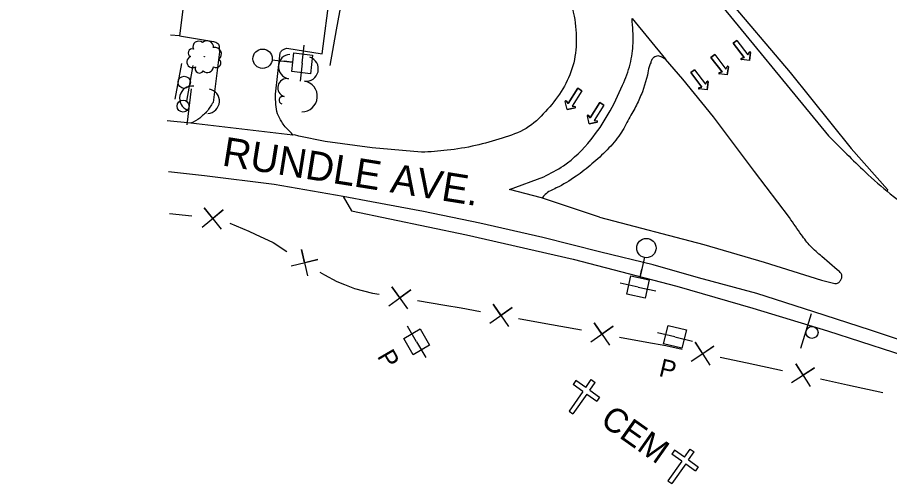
# Model space of a CAD drawing. Extents: x 1746010 to 1754829, y 655801 to 663091.
# Drawn here: x 1748407 to 1748767.9, y 660989.4 to 661182.3 of the extents above; entities that cross this region are included whole.
import ezdxf

# ---------------------------------------------------------------- set-up
doc = ezdxf.new("R2010")
doc.units = 0
for name, color, linetype in [('SURVEY - AERIAL SURVEY - Photo Control - Points - Locators', 7, 'Continuous'), ('SURVEY - AERIAL SURVEY - Photo Control with Text', 7, 'Continuous'), ('SURVEY - CENTERLINE - Existing Roads - Development', 7, 'Continuous'), ('SURVEY - CENTERLINE - Existing Roads Curve Text', 7, 'Continuous'), ('SURVEY - CENTERLINE - Existing Roads Text', 7, 'Continuous'), ('SURVEY - CONTROL - Points - Numbers', 7, 'Continuous'), ('SURVEY - DRAINAGE - Area Shapes - Points - Elevations', 7, 'Continuous')]:
    doc.layers.add(name, color=color, linetype=linetype)

msp = doc.modelspace()

# ---------------------------------------------------------------- linework, layer by layer
at = {"layer": 'SURVEY - AERIAL SURVEY - Photo Control - Points - Locators'}
for points in [[(1748406.97, 661541.06), (1748446.41, 661490.26), (1748508.74, 661414.72), (1748569.86, 661344.49), (1748590.82, 661319.8), (1748726.77, 661159.53), (1748751.93, 661128.01), (1748766.95, 661111.05), (1748766.91, 661110.24)], [(1748543.22, 661365.16), (1748594.47, 661308.59), (1748642.89, 661253.78), (1748692.5, 661194.4), (1748742.62, 661133.3)], [(1748518.42, 661169.62), (1748533.03, 661167.27), (1748536.2, 661191.62), (1748539.76, 661216.56), (1748542.46, 661233.46)], [(1748496.01, 661230.52), (1748481.14, 661231.68), (1748474.06, 661174.67), (1748488.07, 661172.42)], [(1748661.29, 661181.86), (1748675.13, 661165.08)], [(1748490.62, 661168.12), (1748487.93, 661147.18)], [(1748513.7, 661150.58), (1748515.68, 661167.64)], [(1748726.41, 661099.45), (1748712.04, 661118.62), (1748695, 661141.22), (1748682.26, 661156.79), (1748675.13, 661165.08), (1748673.31, 661166.09), (1748672.09, 661166.46)], [(1748667.7, 661158.5), (1748665.59, 661151.48)], [(1748478.78, 661138.57), (1748468.89, 661139.58)], [(1748520.94, 661133.63), (1748478.78, 661138.57)], [(1748574.2, 661126.49), (1748553.7, 661128.42), (1748534.25, 661130.98), (1748523.46, 661133.24), (1748521.67, 661133.71), (1748520.94, 661133.63)], [(1748541.72, 661108.22), (1748513.15, 661113.14), (1748484.42, 661116.74), (1748469.44, 661118.42)], [(1748647.88, 661099.66), (1748623.79, 661107.64), (1748610.62, 661111.11), (1748624.77, 661116.3)], [(1748842.21, 661022.63), (1748822.81, 661030.17), (1748796.81, 661040.14), (1748778.58, 661046.61), (1748759.98, 661052.88), (1748736.59, 661060.44), (1748712.91, 661068.1), (1748688.81, 661074.54), (1748669.98, 661079.87), (1748648.34, 661085.22), (1748624.42, 661091.25), (1748598.28, 661097.15), (1748575.03, 661102), (1748553.53, 661106.02), (1748541.72, 661108.22)], [(1748541.72, 661108.22), (1748545.25, 661102.3), (1748592.74, 661092.3), (1748636.87, 661082.32), (1748679.9, 661071.09), (1748711.25, 661062), (1748742.12, 661052.58), (1748783.15, 661039.32), (1748819.11, 661026.13), (1748839.93, 661016.87), (1748840.62, 661016.6)], [(1748647.88, 661099.66), (1748691.06, 661088.31), (1748715.95, 661081.07), (1748739.71, 661073.63), (1748745.15, 661072.22)], [(1748746.23, 661077.86), (1748739.88, 661083.39)]]:
    msp.add_lwpolyline(points, dxfattribs=at)
for points in [[(1748629.63, 661201.31), (1748633.06, 661195.53), (1748637.33, 661182.83), (1748638.2, 661171.57), (1748636.45, 661161.01), (1748631.94, 661151.62), (1748625.47, 661143.35), (1748617.47, 661136.42), (1748607.57, 661132.33), (1748596.53, 661129.3), (1748584.78, 661127.33), (1748574.2, 661126.49)], [(1748624.77, 661116.3), (1748632.94, 661120.97), (1748644.26, 661131.71), (1748651.45, 661142.23), (1748657.39, 661154.29), (1748660.48, 661163.05), (1748661.7, 661171.73), (1748661.29, 661181.86)], [(1748488.07, 661172.42), (1748489.87, 661171.51), (1748490.34, 661170.87), (1748490.44, 661169.84), (1748490.62, 661168.12)], [(1748515.68, 661167.64), (1748516.49, 661168.78), (1748517.59, 661169.35), (1748518.42, 661169.62)], [(1748672.09, 661166.46), (1748670.33, 661165.75), (1748669.52, 661164.85), (1748669.01, 661163.58), (1748668.41, 661161.94), (1748667.7, 661158.5)], [(1748520.94, 661133.63), (1748519.64, 661135.16), (1748517.74, 661137.06), (1748516.31, 661139.18), (1748514.59, 661142.42), (1748513.94, 661146.26), (1748513.7, 661150.58)], [(1748665.59, 661151.48), (1748663.14, 661146.08), (1748660.02, 661140.39), (1748656.43, 661134.01), (1748651.01, 661127.58), (1748644.7, 661121.67), (1748638.11, 661116.58), (1748629.91, 661111.73), (1748625.35, 661109.05), (1748624.06, 661107.55)], [(1748487.93, 661147.18), (1748486.61, 661145.17), (1748485.47, 661143.47), (1748483.97, 661142.07), (1748482.41, 661140.64), (1748478.78, 661138.57)], [(1748742.62, 661133.3), (1748757.79, 661118.4), (1748768.18, 661109.29), (1748782.04, 661099.44), (1748805.67, 661082.87), (1748823.6, 661073.1), (1748848.74, 661060.68)], [(1748739.88, 661083.39), (1748735.16, 661087.62), (1748731.42, 661092.34), (1748726.41, 661099.45)], [(1748745.15, 661072.22), (1748746.63, 661072.44), (1748747.52, 661073.44), (1748747.89, 661073.96), (1748748.18, 661075.12), (1748747.81, 661076.27), (1748746.23, 661077.86)]]:
    msp.add_spline(points, degree=3, dxfattribs=at)
at = {"layer": 'SURVEY - AERIAL SURVEY - Photo Control with Text'}
for p, q in [((1748472.29, 661148.52), (1748474.99, 661163.28)), ((1748477.01, 661147.66), (1748479.71, 661162.41)), ((1748478.85, 661152.82), (1748477.04, 661137.93)), ((1748731.2, 661045.45), (1748735.62, 661059.79))]:
    msp.add_line(p, q, dxfattribs=at)
for centre, radius in [((1748476, 661155.47), 2.54), ((1748475.5, 661145.63), 2.5), ((1748735.76, 661051.94), 2.5)]:
    msp.add_circle(centre, radius, dxfattribs=at)
at = {"layer": 'SURVEY - CENTERLINE - Existing Roads - Development'}
for p, q in [((1748638.06, 661032.04), (1748636.91, 661030.41)), ((1748642.15, 661029.16), (1748638.06, 661032.04)), ((1748642.15, 661029.16), (1748644.45, 661032.43)), ((1748643.78, 661028.01), (1748646.09, 661031.28)), ((1748644.45, 661032.43), (1748646.09, 661031.28)), ((1748640.99, 661027.53), (1748635.23, 661019.35)), ((1748640.99, 661027.53), (1748636.91, 661030.41)), ((1748643.78, 661028.01), (1748647.87, 661025.12)), ((1748642.63, 661026.37), (1748636.86, 661018.2)), ((1748642.63, 661026.37), (1748646.72, 661023.49)), ((1748647.87, 661025.12), (1748646.72, 661023.49)), ((1748635.23, 661019.35), (1748636.86, 661018.2)), ((1748678.92, 661003.22), (1748677.77, 661001.58)), ((1748683.01, 661000.34), (1748678.92, 661003.22)), ((1748683.01, 661000.34), (1748685.31, 661003.61)), ((1748684.64, 660999.18), (1748686.95, 661002.45)), ((1748685.31, 661003.61), (1748686.95, 661002.45)), ((1748681.85, 660998.7), (1748676.09, 660990.53)), ((1748681.85, 660998.7), (1748677.77, 661001.58)), ((1748684.64, 660999.18), (1748688.73, 660996.3)), ((1748683.49, 660997.55), (1748677.72, 660989.38)), ((1748683.49, 660997.55), (1748687.57, 660994.67)), ((1748688.73, 660996.3), (1748687.57, 660994.67)), ((1748676.09, 660990.53), (1748677.72, 660989.38))]:
    msp.add_line(p, q, dxfattribs=at)
for points in [[(1748540.97, 661188.37), (1748538.92, 661177.16)], [(1748538.92, 661177.16), (1748536.22, 661162.41)], [(1748474.06, 661174.67), (1748470.31, 661175.04)], [(1748483.37, 661095.58), (1748492.11, 661102.64), (1748487.79, 661099.11), (1748484.26, 661103.52), (1748491.22, 661094.71)], [(1748469.9, 661101.15), (1748479.15, 661100.16)], [(1748494.88, 661097.11), (1748502.7, 661093.91), (1748505.36, 661092.64)], [(1748505.36, 661092.64), (1748512.73, 661089.1), (1748518.5, 661085.48)], [(1748520.29, 661079.52), (1748531.24, 661082.08), (1748525.81, 661080.77), (1748524.56, 661086.27), (1748526.97, 661075.32)], [(1748532.12, 661076.92), (1748534.03, 661075.72), (1748539.15, 661073.04), (1748542.27, 661071.78)], [(1748542.27, 661071.78), (1748546.45, 661070.08), (1748553.96, 661068.21), (1748556.66, 661067.77)], [(1748560.61, 661062.96), (1748569.73, 661069.54), (1748565.22, 661066.24), (1748561.94, 661070.83), (1748568.4, 661061.66)], [(1748572.53, 661065.12), (1748583.77, 661063.25)], [(1748583.77, 661063.25), (1748590.58, 661062.11), (1748598.54, 661060.65)], [(1748602.41, 661055.77), (1748611.64, 661062.19), (1748607.07, 661058.97), (1748603.87, 661063.62), (1748610.18, 661054.34)], [(1748614.37, 661057.73), (1748625.58, 661055.67)], [(1748625.58, 661055.67), (1748640.32, 661052.95)], [(1748644.2, 661048.08), (1748653.42, 661054.5), (1748648.86, 661051.28), (1748645.66, 661055.93), (1748651.96, 661046.65)], [(1748656.15, 661050.04), (1748667.36, 661047.97)], [(1748667.36, 661047.97), (1748675.27, 661046.51), (1748682.07, 661045.06)], [(1748685.79, 661040.07), (1748695.2, 661046.22), (1748690.55, 661043.14), (1748687.48, 661047.88), (1748693.51, 661038.42)], [(1748697.8, 661041.69), (1748708.94, 661039.3)], [(1748708.94, 661039.3), (1748723.6, 661036.16)], [(1748727.3, 661031.21), (1748736.75, 661037.3), (1748732.08, 661034.24), (1748729.04, 661039), (1748735.01, 661029.5)], [(1748739.32, 661032.74), (1748750.44, 661030.28)], [(1748750.44, 661030.28), (1748765.08, 661027.04)]]:
    msp.add_lwpolyline(points, dxfattribs=at)
at = {"layer": 'SURVEY - CENTERLINE - Existing Roads Curve Text'}
for p, q in [((1748524.81, 661163.35), (1748525.67, 661170.81)), ((1748512.29, 661164.8), (1748520.94, 661163.8)), ((1748520.54, 661163.85), (1748517.36, 661164.21)), ((1748524.81, 661163.35), (1748523.95, 661155.9)), ((1748666.41, 661083.05), (1748664.59, 661074.54)), ((1748664.67, 661074.94), (1748665.34, 661078.06)), ((1748663.77, 661070.73), (1748656.44, 661072.3)), ((1748663.77, 661070.73), (1748671.11, 661069.16)), ((1748572.16, 661048.06), (1748568.41, 661054.55)), ((1748679.07, 661050.05), (1748671.78, 661051.79)), ((1748679.07, 661050.05), (1748686.37, 661048.32)), ((1748572.16, 661048.06), (1748575.92, 661041.57))]:
    msp.add_line(p, q, dxfattribs=at)
for points in [[(1748528.24, 661159.03), (1748520.49, 661159.93), (1748521.38, 661167.68), (1748529.13, 661166.78)], [(1748659.14, 661067.73), (1748660.77, 661075.36), (1748668.4, 661073.73), (1748666.77, 661066.1)], [(1748573.58, 661053.39), (1748577.49, 661046.64), (1748570.74, 661042.73), (1748566.83, 661049.48)], [(1748676.18, 661054.75), (1748683.77, 661052.95), (1748681.96, 661045.36), (1748674.37, 661047.16)]]:
    msp.add_lwpolyline(points, close=True, dxfattribs=at)
for centre in [(1748508.42, 661165.24), (1748667.23, 661086.87)]:
    msp.add_circle(centre, 4, dxfattribs=at)
at = {"layer": 'SURVEY - CENTERLINE - Existing Roads Text'}
msp.add_circle((1748484.29, 661166.05), 0.0826, dxfattribs=at)
for centre, radius, start, end in [((1748481.94, 661170.15), 2.37, 47.6043, 204.3932), ((1748485.41, 661169.97), 2.7, 356.657, 134.1813), ((1748479.22, 661167.65), 1.63, 69.7205, 248.4661), ((1748488.72, 661167.21), 2.68, 307.5529, 103.3913), ((1748479.42, 661163.91), 2.36, 109.7411, 303.1608), ((1748489.16, 661163.51), 1.98, 237.8058, 52.806), ((1748520.08, 661161.97), 5.1, 94.1554, 259.8138), ((1748520.08, 661161.97), 5.1, 94.1554, 259.8138), ((1748526.38, 661161), 5.1, 262.5893, 71.5564), ((1748526.38, 661161), 5.1, 262.5893, 71.5564), ((1748482.3, 661161.1), 1.8, 152.3598, 329.679), ((1748485.57, 661162.08), 2.55, 227.6469, 354.4925), ((1748518.51, 661153.19), 3.82, 79.8529, 251.5352), ((1748518.51, 661153.19), 3.82, 79.8529, 251.5352), ((1748479.16, 661148.78), 5.1, 81.6232, 250.5903), ((1748479.16, 661148.78), 5.1, 81.6232, 250.5903), ((1748524.7, 661149.67), 6.37, 269.3439, 80.8203), ((1748524.7, 661149.67), 6.37, 269.3439, 80.8203), ((1748485.45, 661147.69), 5.1, 273.2824, 78.9407), ((1748485.45, 661147.69), 5.1, 273.2824, 78.9407), ((1748516.84, 661148.04), 1.59, 73.2454, 253.2454), ((1748516.84, 661148.04), 1.59, 73.2454, 253.2454)]:
    msp.add_arc(centre, radius, start, end, dxfattribs=at)
at = {"layer": 'SURVEY - DRAINAGE - Area Shapes - Points - Elevations'}
for p, q in [((1748703.09, 661171.63), (1748704.65, 661172.83)), ((1748704.65, 661172.83), (1748703.09, 661171.63)), ((1748707.69, 661165.68), (1748703.09, 661171.63)), ((1748703.09, 661171.63), (1748707.69, 661165.68)), ((1748704.65, 661172.83), (1748709.25, 661166.88)), ((1748704.65, 661172.83), (1748709.25, 661166.88)), ((1748709.25, 661166.88), (1748709.86, 661167.95)), ((1748709.25, 661166.88), (1748709.86, 661167.95)), ((1748693.94, 661165.73), (1748695.5, 661166.93)), ((1748695.5, 661166.93), (1748693.94, 661165.73)), ((1748698.54, 661159.77), (1748693.94, 661165.73)), ((1748693.94, 661165.73), (1748698.54, 661159.77)), ((1748695.5, 661166.93), (1748700.1, 661160.97)), ((1748695.5, 661166.93), (1748700.1, 661160.97)), ((1748706.5, 661165.35), (1748707.69, 661165.68)), ((1748707.69, 661165.68), (1748706.5, 661165.35)), ((1748709.89, 661164.44), (1748706.54, 661164.87)), ((1748709.89, 661164.44), (1748706.54, 661164.87)), ((1748710.32, 661167.79), (1748709.89, 661164.44)), ((1748709.89, 661164.44), (1748710.32, 661167.79)), ((1748685.57, 661159.49), (1748687.12, 661160.69)), ((1748687.12, 661160.69), (1748685.57, 661159.49)), ((1748687.12, 661160.69), (1748691.72, 661154.73)), ((1748687.12, 661160.69), (1748691.72, 661154.73)), ((1748700.1, 661160.97), (1748700.71, 661162.04)), ((1748700.1, 661160.97), (1748700.71, 661162.04)), ((1748701.17, 661161.89), (1748700.73, 661158.54)), ((1748700.73, 661158.54), (1748701.17, 661161.89)), ((1748690.16, 661153.53), (1748685.57, 661159.49)), ((1748685.57, 661159.49), (1748690.16, 661153.53)), ((1748697.35, 661159.45), (1748698.54, 661159.77)), ((1748698.54, 661159.77), (1748697.35, 661159.45)), ((1748700.73, 661158.54), (1748697.38, 661158.97)), ((1748700.73, 661158.54), (1748697.38, 661158.97)), ((1748688.98, 661153.21), (1748690.16, 661153.53)), ((1748690.16, 661153.53), (1748688.98, 661153.21)), ((1748691.72, 661154.73), (1748692.33, 661155.8)), ((1748691.72, 661154.73), (1748692.33, 661155.8)), ((1748692.79, 661155.65), (1748692.36, 661152.3)), ((1748692.36, 661152.3), (1748692.79, 661155.65)), ((1748634.82, 661146.68), (1748638.84, 661153.04)), ((1748638.84, 661153.04), (1748634.82, 661146.68)), ((1748640.51, 661151.98), (1748636.48, 661145.63)), ((1748640.51, 661151.98), (1748636.48, 661145.63)), ((1748638.84, 661153.04), (1748640.51, 661151.98)), ((1748640.51, 661151.98), (1748638.84, 661153.04)), ((1748692.36, 661152.3), (1748689.01, 661152.73)), ((1748692.36, 661152.3), (1748689.01, 661152.73)), ((1748634.41, 661144.2), (1748633.67, 661147.49)), ((1748634.41, 661144.2), (1748633.67, 661147.49)), ((1748634.11, 661147.69), (1748634.82, 661146.68)), ((1748634.82, 661146.68), (1748634.11, 661147.69)), ((1748643.94, 661140.74), (1748647.97, 661147.1)), ((1748647.97, 661147.1), (1748643.94, 661140.74)), ((1748647.97, 661147.1), (1748649.63, 661146.04)), ((1748649.63, 661146.04), (1748647.97, 661147.1)), ((1748637.7, 661144.94), (1748634.41, 661144.2)), ((1748634.41, 661144.2), (1748637.7, 661144.94)), ((1748636.48, 661145.63), (1748637.69, 661145.42)), ((1748636.48, 661145.63), (1748637.69, 661145.42)), ((1748649.63, 661146.04), (1748645.61, 661139.69)), ((1748649.63, 661146.04), (1748645.61, 661139.69)), ((1748643.54, 661138.26), (1748642.8, 661141.55)), ((1748643.54, 661138.26), (1748642.8, 661141.55)), ((1748643.24, 661141.75), (1748643.94, 661140.74)), ((1748643.94, 661140.74), (1748643.24, 661141.75)), ((1748646.83, 661139), (1748643.54, 661138.26)), ((1748643.54, 661138.26), (1748646.83, 661139)), ((1748645.61, 661139.69), (1748646.82, 661139.48)), ((1748645.61, 661139.69), (1748646.82, 661139.48))]:
    msp.add_line(p, q, dxfattribs=at)
for centre, start, end in [((1748710.07, 661167.82), 352.6523, 150.1454), ((1748710.07, 661167.82), 352.6523, 150.1454), ((1748706.57, 661165.12), 105.204, 262.6523), ((1748706.57, 661165.12), 105.204, 262.6523), ((1748700.92, 661161.92), 352.6523, 150.1454), ((1748700.92, 661161.92), 352.6523, 150.1454), ((1748697.41, 661159.21), 105.204, 262.6523), ((1748697.41, 661159.21), 105.204, 262.6523), ((1748692.55, 661155.68), 352.6523, 150.1454), ((1748692.55, 661155.68), 352.6523, 150.1454), ((1748689.04, 661152.97), 105.204, 262.6523), ((1748689.04, 661152.97), 105.204, 262.6523), ((1748633.91, 661147.55), 35.1957, 192.644), ((1748633.91, 661147.55), 35.1957, 192.644), ((1748637.65, 661145.18), 282.644, 80.1371), ((1748637.65, 661145.18), 282.644, 80.1371), ((1748643.03, 661141.61), 35.1957, 192.644), ((1748643.03, 661141.61), 35.1957, 192.644), ((1748646.78, 661139.24), 282.644, 80.1371), ((1748646.78, 661139.24), 282.644, 80.1371)]:
    msp.add_arc(centre, 0.246, start, end, dxfattribs=at)

# ---------------------------------------------------------------- texts
at = {"layer": 'SURVEY - CENTERLINE - Existing Roads - Development'}
msp.add_text('CEM', height=10.001, rotation=324.7996, dxfattribs=at).set_placement((1748647.67, 661014.25))
at = {"layer": 'SURVEY - CENTERLINE - Existing Roads Curve Text'}
for rotation, p in [(300.0757, (1748555.64, 661042.08)), (346.6107, (1748672.05, 661033.94))]:
    msp.add_text('P', height=7.48, rotation=rotation, dxfattribs=at).set_placement(p)
at = {"layer": 'SURVEY - CONTROL - Points - Numbers'}
msp.add_text('RUNDLE AVE.', height=12, rotation=350.9508, dxfattribs=at).set_placement((1748491.27, 661121.11))

doc.saveas('drawing.dxf')
